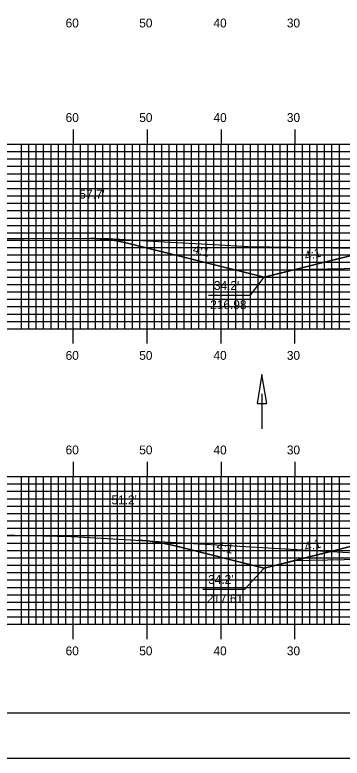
# Model space of a CAD drawing. Extents: x 1820031 to 1820374, y 442591 to 442811.
# Drawn here: x 1820128.8 to 1820173.1, y 442590.5 to 442691.2 of the extents above; entities that cross this region are included whole.
import ezdxf

# ---------------------------------------------------------------- set-up
doc = ezdxf.new("R2010")
doc.units = 0
for name, color, linetype in [('ANNOTATION', 7, 'Continuous'), ('BORDER', 7, 'Continuous'), ('D_Drainage_Ditch_Line', 7, 'Continuous'), ('D_Roadway_Centerline', 7, 'Continuous'), ('D_Roadway_SlopeLines', 7, 'Continuous'), ('D_Roadway_SubGrade', 7, 'Continuous'), ('D_Text_Standard', 7, 'Continuous'), ('H_V ANNOTATION', 7, 'Continuous'), ('MAJOR', 7, 'Continuous'), ('MINOR', 7, 'Continuous'), ('PLOT BOUNDARY', 7, 'Continuous'), ('S_Roadway_Centerline', 7, 'Continuous')]:
    doc.layers.add(name, color=color, linetype=linetype)

msp = doc.modelspace()

# ---------------------------------------------------------------- linework, layer by layer
at = {"layer": 'ANNOTATION'}
for points in [[(1820154.98, 442653.21), (1820160.68, 442653.21), (1820162.52, 442655.65)], [(1820154.2, 442613.41), (1820159.9, 442613.41), (1820162.52, 442616.27)]]:
    msp.add_lwpolyline(points, dxfattribs=at)
at = {"layer": 'BORDER'}
msp.add_lwpolyline([(1820047.09, 442596.67), (1820367.09, 442596.67), (1820367.09, 442806.67), (1820047.09, 442806.67)], close=True, dxfattribs=at)
at = {"layer": 'D_Drainage_Ditch_Line'}
msp.add_line((1820162.22, 442639.85), (1820162.22, 442635.15), dxfattribs=at)
msp.add_lwpolyline([(1820161.57, 442638.54), (1820162.88, 442638.54), (1820162.22, 442642.47)], close=True, dxfattribs=at)
at = {"layer": 'D_Roadway_Centerline'}
for points in [[(1820139.04, 442660.93), (1820140.29, 442660.87), (1820141.54, 442660.75), (1820142.79, 442660.54), (1820144.04, 442660.27), (1820162.52, 442655.65), (1820166.52, 442656.65), (1820176.69, 442659.19), (1820184.69, 442659.51), (1820196.69, 442659.75), (1820208.69, 442659.51), (1820216.69, 442659.19), (1820226.86, 442656.65), (1820230.86, 442655.65), (1820233.98, 442656.43), (1820235.23, 442656.69), (1820236.48, 442656.85), (1820237.73, 442656.9), (1820238.98, 442656.86)], [(1820145.48, 442620.05), (1820146.73, 442619.95), (1820147.98, 442619.79), (1820149.23, 442619.56), (1820150.48, 442619.28), (1820162.52, 442616.27), (1820166.52, 442617.27), (1820176.69, 442619.82), (1820184.69, 442620.14), (1820196.69, 442620.38), (1820208.69, 442620.14), (1820216.69, 442619.82), (1820226.86, 442617.27), (1820232.47, 442615.87)]]:
    msp.add_lwpolyline(points, dxfattribs=at)
at = {"layer": 'D_Roadway_SlopeLines'}
for points in [[(1820162.52, 442655.65), (1820144.04, 442660.27), (1820142.79, 442660.54), (1820141.54, 442660.75), (1820140.29, 442660.87), (1820139.04, 442660.93)], [(1820176.69, 442659.19), (1820162.52, 442655.65)], [(1820162.52, 442616.27), (1820150.48, 442619.28), (1820149.23, 442619.56), (1820147.98, 442619.79), (1820146.73, 442619.95), (1820145.48, 442620.05)], [(1820176.69, 442619.82), (1820162.52, 442616.27)]]:
    msp.add_lwpolyline(points, dxfattribs=at)
at = {"layer": 'D_Roadway_SubGrade'}
for points in [[(1820184.69, 442657.01), (1820166.52, 442656.65), (1820176.69, 442659.19), (1820176.69, 442658.94), (1820184.69, 442659.26), (1820196.69, 442659.5), (1820208.69, 442659.26), (1820216.69, 442658.94), (1820216.69, 442659.19), (1820226.86, 442656.65), (1820208.69, 442657.01), (1820196.69, 442657.25)], [(1820184.69, 442617.64), (1820166.52, 442617.27), (1820176.69, 442619.82), (1820176.69, 442619.57), (1820184.69, 442619.89), (1820196.69, 442620.13), (1820208.69, 442619.89), (1820216.69, 442619.57), (1820216.69, 442619.82), (1820226.86, 442617.27), (1820208.69, 442617.64), (1820196.69, 442617.88)]]:
    msp.add_lwpolyline(points, close=True, dxfattribs=at)
at = {"layer": 'MAJOR'}
for p, q in [((1820136.69, 442675.67), (1820136.69, 442673.67)), ((1820146.69, 442675.67), (1820146.69, 442673.67)), ((1820156.69, 442675.67), (1820156.69, 442673.67)), ((1820166.69, 442675.67), (1820166.69, 442673.67)), ((1820056.69, 442673.67), (1820336.69, 442673.67)), ((1820056.69, 442673.67), (1820336.69, 442673.67)), ((1820136.69, 442648.67), (1820136.69, 442673.67)), ((1820146.69, 442648.67), (1820146.69, 442673.67)), ((1820156.69, 442648.67), (1820156.69, 442673.67)), ((1820166.69, 442648.67), (1820166.69, 442673.67)), ((1820056.69, 442668.67), (1820336.69, 442668.67)), ((1820056.69, 442663.67), (1820336.69, 442663.67)), ((1820056.69, 442658.67), (1820336.69, 442658.67)), ((1820056.69, 442653.67), (1820336.69, 442653.67)), ((1820056.69, 442648.67), (1820336.69, 442648.67)), ((1820056.69, 442648.67), (1820336.69, 442648.67)), ((1820136.69, 442646.66), (1820136.69, 442648.67)), ((1820146.69, 442646.66), (1820146.69, 442648.67)), ((1820156.69, 442646.66), (1820156.69, 442648.67)), ((1820166.69, 442646.66), (1820166.69, 442648.67)), ((1820136.69, 442630.67), (1820136.69, 442628.67)), ((1820146.69, 442630.67), (1820146.69, 442628.67)), ((1820156.69, 442630.67), (1820156.69, 442628.67)), ((1820166.69, 442630.67), (1820166.69, 442628.67)), ((1820056.69, 442628.67), (1820336.69, 442628.67)), ((1820056.69, 442628.67), (1820336.69, 442628.67)), ((1820136.69, 442608.67), (1820136.69, 442628.67)), ((1820146.69, 442608.67), (1820146.69, 442628.67)), ((1820156.69, 442608.67), (1820156.69, 442628.67)), ((1820166.69, 442608.67), (1820166.69, 442628.67)), ((1820056.69, 442623.67), (1820336.69, 442623.67)), ((1820056.69, 442618.67), (1820336.69, 442618.67)), ((1820056.69, 442613.67), (1820336.69, 442613.67)), ((1820056.69, 442608.67), (1820336.69, 442608.67)), ((1820056.69, 442608.67), (1820336.69, 442608.67)), ((1820136.69, 442606.66), (1820136.69, 442608.67)), ((1820146.69, 442606.66), (1820146.69, 442608.67)), ((1820156.69, 442606.66), (1820156.69, 442608.67)), ((1820166.69, 442606.66), (1820166.69, 442608.67))]:
    msp.add_line(p, q, dxfattribs=at)
at = {"layer": 'MINOR'}
for p, q in [((1820129.69, 442648.67), (1820129.69, 442673.67)), ((1820130.69, 442648.67), (1820130.69, 442673.67)), ((1820131.69, 442648.67), (1820131.69, 442673.67)), ((1820132.69, 442648.67), (1820132.69, 442673.67)), ((1820133.69, 442648.67), (1820133.69, 442673.67)), ((1820134.69, 442648.67), (1820134.69, 442673.67)), ((1820135.69, 442648.67), (1820135.69, 442673.67)), ((1820137.69, 442648.67), (1820137.69, 442673.67)), ((1820138.69, 442648.67), (1820138.69, 442673.67)), ((1820139.69, 442648.67), (1820139.69, 442673.67)), ((1820140.69, 442648.67), (1820140.69, 442673.67)), ((1820141.69, 442648.67), (1820141.69, 442673.67)), ((1820142.69, 442648.67), (1820142.69, 442673.67)), ((1820143.69, 442648.67), (1820143.69, 442673.67)), ((1820144.69, 442648.67), (1820144.69, 442673.67)), ((1820145.69, 442648.67), (1820145.69, 442673.67)), ((1820147.69, 442648.67), (1820147.69, 442673.67)), ((1820148.69, 442648.67), (1820148.69, 442673.67)), ((1820149.69, 442648.67), (1820149.69, 442673.67)), ((1820150.69, 442648.67), (1820150.69, 442673.67)), ((1820151.69, 442648.67), (1820151.69, 442673.67)), ((1820152.69, 442648.67), (1820152.69, 442673.67)), ((1820153.69, 442648.67), (1820153.69, 442673.67)), ((1820154.69, 442648.67), (1820154.69, 442673.67)), ((1820155.69, 442648.67), (1820155.69, 442673.67)), ((1820157.69, 442648.67), (1820157.69, 442673.67)), ((1820158.69, 442648.67), (1820158.69, 442673.67)), ((1820159.69, 442648.67), (1820159.69, 442673.67)), ((1820160.69, 442648.67), (1820160.69, 442673.67)), ((1820161.69, 442648.67), (1820161.69, 442673.67)), ((1820162.69, 442648.67), (1820162.69, 442673.67)), ((1820163.69, 442648.67), (1820163.69, 442673.67)), ((1820164.69, 442648.67), (1820164.69, 442673.67)), ((1820165.69, 442648.67), (1820165.69, 442673.67)), ((1820167.69, 442648.67), (1820167.69, 442673.67)), ((1820168.69, 442648.67), (1820168.69, 442673.67)), ((1820169.69, 442648.67), (1820169.69, 442673.67)), ((1820170.69, 442648.67), (1820170.69, 442673.67)), ((1820171.69, 442648.67), (1820171.69, 442673.67)), ((1820172.69, 442648.67), (1820172.69, 442673.67)), ((1820056.69, 442672.67), (1820336.69, 442672.67)), ((1820056.69, 442671.67), (1820336.69, 442671.67)), ((1820056.69, 442670.67), (1820336.69, 442670.67)), ((1820056.69, 442669.67), (1820336.69, 442669.67)), ((1820056.69, 442667.67), (1820336.69, 442667.67)), ((1820056.69, 442666.67), (1820336.69, 442666.67)), ((1820056.69, 442665.67), (1820336.69, 442665.67)), ((1820056.69, 442664.67), (1820336.69, 442664.67)), ((1820056.69, 442662.67), (1820336.69, 442662.67)), ((1820056.69, 442661.67), (1820336.69, 442661.67)), ((1820056.69, 442660.67), (1820336.69, 442660.67)), ((1820056.69, 442659.67), (1820336.69, 442659.67)), ((1820056.69, 442657.67), (1820336.69, 442657.67)), ((1820056.69, 442656.67), (1820336.69, 442656.67)), ((1820056.69, 442655.67), (1820336.69, 442655.67)), ((1820056.69, 442654.67), (1820336.69, 442654.67)), ((1820056.69, 442652.67), (1820336.69, 442652.67)), ((1820056.69, 442651.67), (1820336.69, 442651.67)), ((1820056.69, 442650.67), (1820336.69, 442650.67)), ((1820056.69, 442649.67), (1820336.69, 442649.67)), ((1820129.69, 442608.67), (1820129.69, 442628.67)), ((1820130.69, 442608.67), (1820130.69, 442628.67)), ((1820131.69, 442608.67), (1820131.69, 442628.67)), ((1820132.69, 442608.67), (1820132.69, 442628.67)), ((1820133.69, 442608.67), (1820133.69, 442628.67)), ((1820134.69, 442608.67), (1820134.69, 442628.67)), ((1820135.69, 442608.67), (1820135.69, 442628.67)), ((1820137.69, 442608.67), (1820137.69, 442628.67)), ((1820138.69, 442608.67), (1820138.69, 442628.67)), ((1820139.69, 442608.67), (1820139.69, 442628.67)), ((1820140.69, 442608.67), (1820140.69, 442628.67)), ((1820141.69, 442608.67), (1820141.69, 442628.67)), ((1820142.69, 442608.67), (1820142.69, 442628.67)), ((1820143.69, 442608.67), (1820143.69, 442628.67)), ((1820144.69, 442608.67), (1820144.69, 442628.67)), ((1820145.69, 442608.67), (1820145.69, 442628.67)), ((1820147.69, 442608.67), (1820147.69, 442628.67)), ((1820148.69, 442608.67), (1820148.69, 442628.67)), ((1820149.69, 442608.67), (1820149.69, 442628.67)), ((1820150.69, 442608.67), (1820150.69, 442628.67)), ((1820151.69, 442608.67), (1820151.69, 442628.67)), ((1820152.69, 442608.67), (1820152.69, 442628.67)), ((1820153.69, 442608.67), (1820153.69, 442628.67)), ((1820154.69, 442608.67), (1820154.69, 442628.67)), ((1820155.69, 442608.67), (1820155.69, 442628.67)), ((1820157.69, 442608.67), (1820157.69, 442628.67)), ((1820158.69, 442608.67), (1820158.69, 442628.67)), ((1820159.69, 442608.67), (1820159.69, 442628.67)), ((1820160.69, 442608.67), (1820160.69, 442628.67)), ((1820161.69, 442608.67), (1820161.69, 442628.67)), ((1820162.69, 442608.67), (1820162.69, 442628.67)), ((1820163.69, 442608.67), (1820163.69, 442628.67)), ((1820164.69, 442608.67), (1820164.69, 442628.67)), ((1820165.69, 442608.67), (1820165.69, 442628.67)), ((1820167.69, 442608.67), (1820167.69, 442628.67)), ((1820168.69, 442608.67), (1820168.69, 442628.67)), ((1820169.69, 442608.67), (1820169.69, 442628.67)), ((1820170.69, 442608.67), (1820170.69, 442628.67)), ((1820171.69, 442608.67), (1820171.69, 442628.67)), ((1820172.69, 442608.67), (1820172.69, 442628.67)), ((1820056.69, 442627.67), (1820336.69, 442627.67)), ((1820056.69, 442626.67), (1820336.69, 442626.67)), ((1820056.69, 442625.67), (1820336.69, 442625.67)), ((1820056.69, 442624.67), (1820336.69, 442624.67)), ((1820056.69, 442622.67), (1820336.69, 442622.67)), ((1820056.69, 442621.67), (1820336.69, 442621.67)), ((1820056.69, 442620.67), (1820336.69, 442620.67)), ((1820056.69, 442619.67), (1820336.69, 442619.67)), ((1820056.69, 442617.67), (1820336.69, 442617.67)), ((1820056.69, 442616.67), (1820336.69, 442616.67)), ((1820056.69, 442615.67), (1820336.69, 442615.67)), ((1820056.69, 442614.67), (1820336.69, 442614.67)), ((1820056.69, 442612.67), (1820336.69, 442612.67)), ((1820056.69, 442611.67), (1820336.69, 442611.67)), ((1820056.69, 442610.67), (1820336.69, 442610.67)), ((1820056.69, 442609.67), (1820336.69, 442609.67))]:
    msp.add_line(p, q, dxfattribs=at)
at = {"layer": 'PLOT BOUNDARY'}
msp.add_lwpolyline([(1820030.9, 442590.55), (1820370.9, 442590.55), (1820370.9, 442810.55), (1820030.9, 442810.55)], close=True, dxfattribs=at)
at = {"layer": 'S_Roadway_Centerline'}
for points in [[(1820056.69, 442664.03), (1820057, 442664.03), (1820063.6, 442662.91), (1820081.74, 442662.45), (1820101.72, 442662.02), (1820110.61, 442661.61), (1820124.72, 442660.91), (1820130.07, 442660.88), (1820140.73, 442660.94), (1820148.98, 442660.46), (1820155.71, 442660.07), (1820160.35, 442659.82), (1820174.75, 442659.57), (1820182.84, 442659.24), (1820191.56, 442658.58), (1820196.32, 442658.43), (1820208.93, 442657.64), (1820224, 442657.83), (1820229.94, 442657.56), (1820241.99, 442656.62), (1820249.22, 442656.31), (1820259.82, 442656.42)], [(1820056.69, 442622.61), (1820064.68, 442621.85), (1820076.04, 442621.85), (1820086.41, 442621.89), (1820099.23, 442621.29), (1820102.31, 442621.14), (1820107.46, 442621.06), (1820119.88, 442620.93), (1820126.83, 442620.76), (1820136.4, 442620.57), (1820138.18, 442620.48), (1820181.73, 442617.93), (1820187.68, 442617.59), (1820190.87, 442617.6), (1820193.69, 442617.4), (1820212.26, 442616.7), (1820222.13, 442616.12), (1820232.29, 442615.88), (1820248.06, 442615.29), (1820255.72, 442615.2)]]:
    msp.add_lwpolyline(points, dxfattribs=at)

# ---------------------------------------------------------------- texts
at = {"layer": 'ANNOTATION'}
for rotation, p in [(345.9638, (1820152.78, 442658.94)), (14.0362, (1820168.14, 442657.92)), (345.9638, (1820156, 442618.76)), (14.0362, (1820168.14, 442618.54))]:
    msp.add_text('4:1', height=1.2, rotation=rotation, dxfattribs=at).set_placement(p)
for s, p in [("34.2'", (1820155.72, 442653.93)), ('216.98', (1820155.22, 442651.33)), ("34.2'", (1820154.94, 442614.14)), ('217.61', (1820154.76, 442611.54))]:
    msp.add_text(s, height=1.2, dxfattribs=at).set_placement(p)
at = {"layer": 'D_Text_Standard'}
for s, p in [("57.7'", (1820137.53, 442666.29)), ("51.2'", (1820141.86, 442624.91))]:
    msp.add_text(s, height=1.2, dxfattribs=at).set_placement(p)
at = {"layer": 'H_V ANNOTATION'}
for s, p in [('60', (1820135.66, 442689.47)), ('50', (1820145.62, 442689.47)), ('40', (1820155.66, 442689.47)), ('30', (1820165.59, 442689.47)), ('60', (1820135.66, 442676.67)), ('50', (1820145.62, 442676.67)), ('40', (1820155.66, 442676.67)), ('30', (1820165.59, 442676.67)), ('60', (1820135.66, 442644.47)), ('50', (1820145.62, 442644.47)), ('40', (1820155.66, 442644.47)), ('30', (1820165.59, 442644.47)), ('60', (1820135.66, 442631.67)), ('50', (1820145.62, 442631.67)), ('40', (1820155.66, 442631.67)), ('30', (1820165.59, 442631.67)), ('60', (1820135.66, 442604.47)), ('50', (1820145.62, 442604.47)), ('40', (1820155.66, 442604.47)), ('30', (1820165.59, 442604.47))]:
    msp.add_text(s, height=1.2, dxfattribs=at).set_placement(p)

doc.saveas('drawing.dxf')
